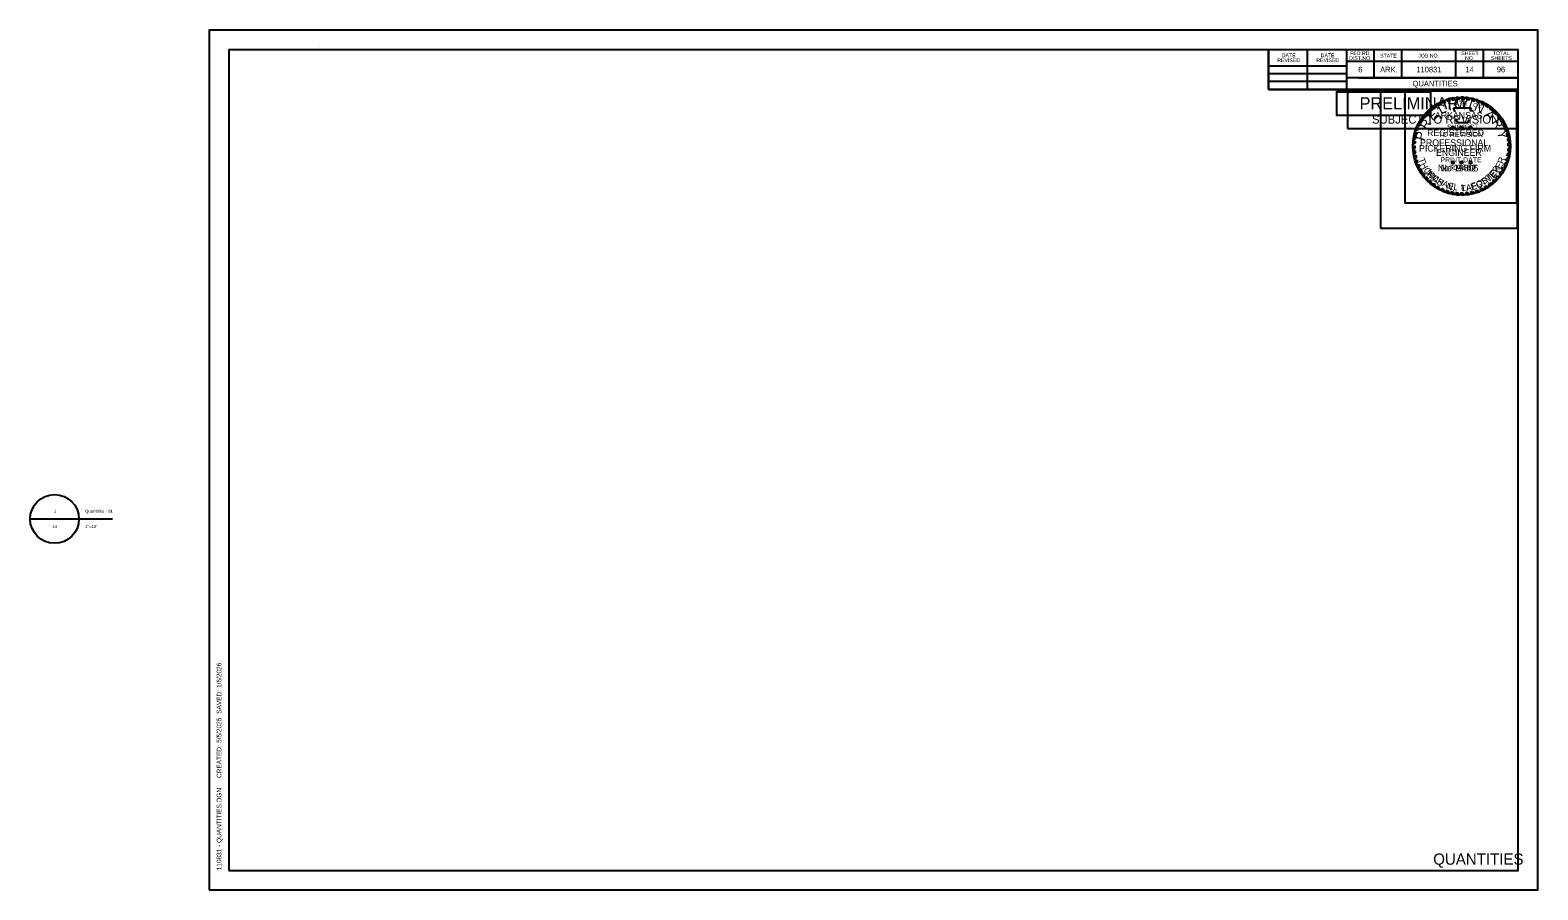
# Model space of a CAD drawing. Extents: x -0.19 to 1.42, y 0 to 0.92.
import ezdxf

# ---------------------------------------------------------------- set-up
doc = ezdxf.new("R2010")
doc.units = 0
for name, color, linetype in [('Default', 7, 'Continuous'), ('DSN_DRFT_Guideline-No-Plot', 7, 'Continuous'), ('SHET_Annotations', 7, 'Continuous'), ('SHET_Border-Lines', 7, 'Continuous'), ('SHET_Border-Text', 7, 'Continuous'), ('SHET_Stamp-Prelim', 7, 'Continuous'), ('SHET_Stamp-Seal', 7, 'Continuous'), ('STAMP_PE DIG SIG', 7, 'Continuous'), ('STAMP_PE_BACKGROUND', 7, 'Continuous'), ('STAMP_PE_FOSTER', 7, 'Continuous'), ('STAMP_PE_SEAL-INFO', 7, 'Continuous'), ('STAMP_PE_TAEGTMEYER', 7, 'Continuous'), ('STAMP_PRELIMINARY', 7, 'Continuous')]:
    doc.layers.add(name, color=color, linetype=linetype)

msp = doc.modelspace()

# ---------------------------------------------------------------- linework, layer by layer
at = {"layer": 'Default'}
for p, q in [((-0.191, 0.3955), (-0.1389, 0.3955)), ((-0.1648, 0.3955), (-0.1031, 0.3955))]:
    msp.add_line(p, q, dxfattribs=at)
msp.add_circle((-0.165, 0.3955), 0.026, dxfattribs=at)
at = {"layer": 'DSN_DRFT_Guideline-No-Plot'}
msp.add_lwpolyline([(0, 0), (1.4167, 0), (1.4167, 0.9167), (0, 0.9167)], close=True, dxfattribs=at)
at = {"layer": 'SHET_Border-Lines'}
for p, q in [((0.1176, 0.8988), (0.1176, 0.8988)), ((0.1176, 0.8988), (0.1176, 0.8988)), ((1.1296, 0.8534), (1.1296, 0.8958)), ((1.1711, 0.8534), (1.1711, 0.8958)), ((1.2127, 0.8958), (1.2127, 0.8534)), ((1.2417, 0.8958), (1.2417, 0.866)), ((1.2712, 0.8958), (1.2712, 0.866)), ((1.3289, 0.8958), (1.3289, 0.866)), ((1.3584, 0.8958), (1.3584, 0.866)), ((1.1296, 0.8786), (1.2127, 0.8786)), ((1.1296, 0.8706), (1.2127, 0.8706)), ((1.3958, 0.8832), (1.2127, 0.8832)), ((1.3958, 0.8833), (1.3958, 0.8833)), ((1.1296, 0.8622), (1.2127, 0.8622)), ((1.3958, 0.8534), (1.1296, 0.8534)), ((1.3958, 0.866), (1.2127, 0.866)), ((1.2252, 0.866), (1.3958, 0.866))]:
    msp.add_line(p, q, dxfattribs=at)
for points in [[(0.0208, 0.0208), (1.3958, 0.0208), (1.3958, 0.8958), (0.0208, 0.8958)], [(1.1296, 0.8534), (1.3958, 0.8534), (1.3958, 0.8958), (1.1296, 0.8958)]]:
    msp.add_lwpolyline(points, close=True, dxfattribs=at)
at = {"layer": 'SHET_Stamp-Prelim'}
msp.add_lwpolyline([(1.2137, 0.8119), (1.3948, 0.8119), (1.3948, 0.8524), (1.2137, 0.8524)], close=True, dxfattribs=at)
at = {"layer": 'SHET_Stamp-Seal'}
msp.add_line((1.3219, 0.7895), (1.3219, 0.7895), dxfattribs=at)
msp.add_lwpolyline([(1.249, 0.7057), (1.3948, 0.7057), (1.3948, 0.8524), (1.249, 0.8524)], close=True, dxfattribs=at)
at = {"layer": 'STAMP_PE DIG SIG'}
msp.add_lwpolyline([(1.2022, 0.8508), (1.3022, 0.8508), (1.3022, 0.8258), (1.2022, 0.8258)], close=True, dxfattribs=at)
at = {"layer": 'STAMP_PE_BACKGROUND'}
for points in [[(1.2022, 0.8517), (1.3022, 0.8517), (1.3022, 0.8258), (1.2022, 0.8258)], [(1.3942, 0.8517), (1.275, 0.8517), (1.275, 0.7325), (1.3942, 0.7325)]]:
    msp.add_lwpolyline(points, close=True, dxfattribs=at)
at = {"layer": 'STAMP_PE_SEAL-INFO'}
for p, q in [((1.3066, 0.8363), (1.309, 0.8352)), ((1.3087, 0.8377), (1.3112, 0.8365)), ((1.3112, 0.8391), (1.3138, 0.8378)), ((1.3137, 0.8403), (1.3158, 0.8387)), ((1.3165, 0.8415), (1.3181, 0.8397)), ((1.3184, 0.8422), (1.3206, 0.8405)), ((1.3217, 0.8432), (1.3233, 0.8413)), ((1.3239, 0.8438), (1.3259, 0.8418)), ((1.3266, 0.8443), (1.3283, 0.8422)), ((1.3295, 0.8447), (1.331, 0.8426)), ((1.3336, 0.8427), (1.3318, 0.8449)), ((1.3364, 0.8428), (1.3348, 0.845)), ((1.3389, 0.8426), (1.3375, 0.845)), ((1.3417, 0.8424), (1.3401, 0.8448)), ((1.3441, 0.842), (1.3427, 0.8445)), ((1.3473, 0.8413), (1.3463, 0.8439)), ((1.3495, 0.8407), (1.3486, 0.8433)), ((1.352, 0.8399), (1.3512, 0.8426)), ((1.3544, 0.839), (1.3536, 0.8418)), ((1.357, 0.8379), (1.3564, 0.8406)), ((1.3594, 0.8366), (1.359, 0.8394)), ((1.3616, 0.8353), (1.3614, 0.8381)), ((1.364, 0.8337), (1.3639, 0.8366)), ((1.2917, 0.8213), (1.2946, 0.8215)), ((1.293, 0.8232), (1.2959, 0.8232)), ((1.2946, 0.8253), (1.2977, 0.8254)), ((1.2965, 0.8276), (1.2994, 0.8274)), ((1.2983, 0.8295), (1.3014, 0.8293)), ((1.3002, 0.8313), (1.3028, 0.8306)), ((1.3021, 0.833), (1.3051, 0.8325)), ((1.3042, 0.8348), (1.3068, 0.8337)), ((1.3269, 0.8337), (1.3456, 0.8337)), ((1.3276, 0.832), (1.3269, 0.8337)), ((1.3281, 0.8303), (1.3276, 0.832)), ((1.3282, 0.8297), (1.3281, 0.8303)), ((1.3293, 0.8201), (1.3291, 0.8213)), ((1.331, 0.8201), (1.3293, 0.8201)), ((1.331, 0.8177), (1.331, 0.8201)), ((1.3429, 0.8213), (1.3424, 0.8196)), ((1.3456, 0.8337), (1.3443, 0.831)), ((1.3443, 0.831), (1.3478, 0.831)), ((1.3478, 0.831), (1.347, 0.8297)), ((1.366, 0.8322), (1.3662, 0.8349)), ((1.3685, 0.8301), (1.3687, 0.8331)), ((1.3703, 0.8285), (1.3707, 0.8313)), ((1.3723, 0.8264), (1.3727, 0.8294)), ((1.3738, 0.8247), (1.3746, 0.8273)), ((1.3756, 0.8223), (1.3764, 0.8251)), ((1.3769, 0.8206), (1.3779, 0.8232)), ((1.3786, 0.8178), (1.3796, 0.8205)), ((1.2847, 0.8048), (1.2873, 0.8059)), ((1.2853, 0.8071), (1.2879, 0.808)), ((1.2862, 0.8099), (1.2889, 0.8106)), ((1.287, 0.8121), (1.2898, 0.8129)), ((1.288, 0.8145), (1.2908, 0.8151)), ((1.2891, 0.8167), (1.2918, 0.8171)), ((1.2904, 0.8191), (1.2931, 0.8192)), ((1.3252, 0.8129), (1.3241, 0.8137)), ((1.3241, 0.8137), (1.3255, 0.8137)), ((1.3248, 0.8116), (1.3252, 0.8129)), ((1.3259, 0.8124), (1.3248, 0.8116)), ((1.3255, 0.8137), (1.3259, 0.815)), ((1.3259, 0.815), (1.3264, 0.8137)), ((1.327, 0.8116), (1.3259, 0.8124)), ((1.3264, 0.8137), (1.3277, 0.8137)), ((1.3277, 0.8137), (1.3266, 0.8129)), ((1.3266, 0.8129), (1.327, 0.8116)), ((1.3423, 0.8177), (1.331, 0.8177)), ((1.3347, 0.8129), (1.3336, 0.8137)), ((1.3336, 0.8137), (1.335, 0.8137)), ((1.3343, 0.8116), (1.3347, 0.8129)), ((1.3354, 0.8124), (1.3343, 0.8116)), ((1.335, 0.8137), (1.3354, 0.815)), ((1.3354, 0.815), (1.3358, 0.8137)), ((1.3365, 0.8116), (1.3354, 0.8124)), ((1.3358, 0.8137), (1.3372, 0.8137)), ((1.3372, 0.8137), (1.3361, 0.8129)), ((1.3361, 0.8129), (1.3365, 0.8116)), ((1.3424, 0.8196), (1.3423, 0.8177)), ((1.3442, 0.8129), (1.3431, 0.8137)), ((1.3431, 0.8137), (1.3445, 0.8137)), ((1.3438, 0.8116), (1.3442, 0.8129)), ((1.3449, 0.8124), (1.3438, 0.8116)), ((1.3445, 0.8137), (1.3449, 0.815)), ((1.3449, 0.815), (1.3453, 0.8137)), ((1.346, 0.8116), (1.3449, 0.8124)), ((1.3453, 0.8137), (1.3467, 0.8137)), ((1.3467, 0.8137), (1.3456, 0.8129)), ((1.3456, 0.8129), (1.346, 0.8116)), ((1.3797, 0.8157), (1.381, 0.8182)), ((1.381, 0.813), (1.3823, 0.8157)), ((1.3818, 0.8112), (1.3832, 0.8136)), ((1.3829, 0.8081), (1.3844, 0.8107)), ((1.3835, 0.8061), (1.3851, 0.8086)), ((1.3842, 0.8029), (1.386, 0.8054)), ((1.2857, 0.796), (1.2834, 0.7946)), ((1.2856, 0.7933), (1.2834, 0.7914)), ((1.2859, 0.7984), (1.2835, 0.7968)), ((1.2857, 0.791), (1.2835, 0.7892)), ((1.2862, 0.8008), (1.2838, 0.7996)), ((1.2858, 0.7882), (1.2838, 0.7862)), ((1.2867, 0.8034), (1.2841, 0.802)), ((1.3846, 0.8008), (1.3866, 0.8028)), ((1.3849, 0.7876), (1.3874, 0.7891)), ((1.385, 0.798), (1.387, 0.7998)), ((1.3851, 0.7956), (1.3873, 0.7973)), ((1.3852, 0.7927), (1.3875, 0.7945)), ((1.3852, 0.7905), (1.3875, 0.792)), ((1.2861, 0.7858), (1.2842, 0.7837)), ((1.2866, 0.7833), (1.2847, 0.7812)), ((1.2871, 0.7809), (1.2854, 0.7786)), ((1.2878, 0.7784), (1.2861, 0.7761)), ((1.2886, 0.7761), (1.287, 0.7738)), ((1.2895, 0.7737), (1.288, 0.7713)), ((1.3252, 0.7754), (1.3241, 0.7763)), ((1.3241, 0.7763), (1.3255, 0.7763)), ((1.3248, 0.7741), (1.3252, 0.7754)), ((1.3259, 0.7749), (1.3248, 0.7741)), ((1.3255, 0.7763), (1.3259, 0.7776)), ((1.3259, 0.7776), (1.3264, 0.7763)), ((1.327, 0.7741), (1.3259, 0.7749)), ((1.3264, 0.7763), (1.3277, 0.7763)), ((1.3277, 0.7763), (1.3266, 0.7754)), ((1.3266, 0.7754), (1.327, 0.7741)), ((1.3347, 0.7754), (1.3336, 0.7763)), ((1.3336, 0.7763), (1.335, 0.7763)), ((1.3343, 0.7741), (1.3347, 0.7754)), ((1.3354, 0.7749), (1.3343, 0.7741)), ((1.335, 0.7763), (1.3354, 0.7776)), ((1.3354, 0.7776), (1.3358, 0.7763)), ((1.3365, 0.7741), (1.3354, 0.7749)), ((1.3358, 0.7763), (1.3372, 0.7763)), ((1.3372, 0.7763), (1.3361, 0.7754)), ((1.3361, 0.7754), (1.3365, 0.7741)), ((1.3442, 0.7754), (1.3431, 0.7763)), ((1.3431, 0.7763), (1.3445, 0.7763)), ((1.3438, 0.7741), (1.3442, 0.7754)), ((1.3449, 0.7749), (1.3438, 0.7741)), ((1.3445, 0.7763), (1.3449, 0.7776)), ((1.3449, 0.7776), (1.3453, 0.7763)), ((1.346, 0.7741), (1.3449, 0.7749)), ((1.3453, 0.7763), (1.3467, 0.7763)), ((1.3467, 0.7763), (1.3456, 0.7754)), ((1.3456, 0.7754), (1.346, 0.7741)), ((1.3808, 0.7724), (1.3835, 0.7729)), ((1.382, 0.7753), (1.3847, 0.776)), ((1.3827, 0.7774), (1.3855, 0.7785)), ((1.3835, 0.7802), (1.3862, 0.7813)), ((1.3841, 0.7827), (1.3867, 0.7838)), ((1.3846, 0.7855), (1.3871, 0.7867)), ((1.2905, 0.7715), (1.2892, 0.769)), ((1.2918, 0.769), (1.2907, 0.7662)), ((1.2931, 0.7667), (1.2921, 0.7641)), ((1.2942, 0.765), (1.2936, 0.7619)), ((1.2958, 0.7628), (1.2952, 0.7598)), ((1.2975, 0.7607), (1.297, 0.7578)), ((1.2992, 0.7588), (1.2988, 0.7559)), ((1.301, 0.757), (1.3008, 0.754)), ((1.3702, 0.7573), (1.3727, 0.7566)), ((1.3716, 0.7588), (1.3743, 0.7583)), ((1.3738, 0.7612), (1.3763, 0.7608)), ((1.3755, 0.7634), (1.3783, 0.7634)), ((1.3774, 0.7662), (1.3801, 0.7661)), ((1.3783, 0.7677), (1.3811, 0.768)), ((1.3799, 0.7705), (1.3826, 0.7709)), ((1.3029, 0.7552), (1.3029, 0.7523)), ((1.3049, 0.7536), (1.305, 0.7507)), ((1.3068, 0.7522), (1.307, 0.7493)), ((1.3092, 0.7506), (1.3095, 0.7478)), ((1.3111, 0.7495), (1.3117, 0.7466)), ((1.3138, 0.7481), (1.3147, 0.7452)), ((1.3159, 0.7471), (1.3169, 0.7443)), ((1.3187, 0.7461), (1.3198, 0.7433)), ((1.321, 0.7453), (1.3222, 0.7426)), ((1.3238, 0.7445), (1.325, 0.7419)), ((1.326, 0.7441), (1.3274, 0.7415)), ((1.3288, 0.7436), (1.3302, 0.7411)), ((1.3313, 0.7433), (1.3328, 0.7409)), ((1.334, 0.7432), (1.3356, 0.7409)), ((1.3365, 0.7432), (1.3384, 0.741)), ((1.3394, 0.7433), (1.3412, 0.7412)), ((1.3419, 0.7436), (1.344, 0.7416)), ((1.3444, 0.744), (1.3465, 0.7421)), ((1.3471, 0.7446), (1.3492, 0.7427)), ((1.3497, 0.7453), (1.352, 0.7436)), ((1.3524, 0.7462), (1.3549, 0.7447)), ((1.3548, 0.7471), (1.3571, 0.7456)), ((1.3573, 0.7483), (1.36, 0.7471)), ((1.3596, 0.7494), (1.3619, 0.7481)), ((1.3619, 0.7508), (1.3644, 0.7497)), ((1.3639, 0.7521), (1.3663, 0.751)), ((1.3664, 0.754), (1.369, 0.7532)), ((1.3679, 0.7553), (1.3706, 0.7545))]:
    msp.add_line(p, q, dxfattribs=at)
for radius, start, end in [(0.0521, 123.6199, 126.5906), (0.0521, 117.6544, 120.8099), (0.0498, 115.6869, 119.1583), (0.0521, 111.3124, 114.7026), (0.0498, 110.3086, 113.1659), (0.0521, 105.2339, 109.0352), (0.0498, 104.0352, 107.3615), (0.0521, 99.7525, 102.7765), (0.0498, 98.258, 101.0329), (0.0521, 93.9381, 96.5517), (0.0498, 92.1102, 95.0367), (0.0521, 87.7298, 90.6707), (0.0498, 85.9628, 88.9097), (0.0521, 81.9732, 84.8236), (0.0498, 79.9264, 82.696), (0.0521, 75.3125, 77.9426), (0.0498, 73.5575, 76.2314), (0.0521, 69.6061, 72.3058), (0.0498, 67.6248, 70.504), (0.0521, 63.1329, 66.2704), (0.0498, 61.1558, 64.3784), (0.0521, 56.9003, 60.0942), (0.0521, 147.0072, 149.899), (0.0521, 141.6056, 144.4486), (0.0498, 145.0197, 148.2104), (0.0498, 139.301, 142.5873), (0.0521, 135.4021, 138.3031), (0.0498, 133.1331, 136.2562), (0.0521, 129.7326, 132.5376), (0.0498, 127.5297, 130.9683), (0.0498, 121.9746, 125.11), (0.0498, 54.9238, 58.2702), (0.0498, 48.3016, 52.0395), (0.0521, 50.3492, 53.7159), (0.0498, 42.2212, 45.5512), (0.0521, 44.3405, 47.3929), (0.0498, 36.135, 39.5311), (0.0521, 38.1247, 41.2316), (0.0498, 29.9032, 33.6645), (0.0521, 31.9614, 35.4294), (0.0521, 164.3068, 166.894), (0.0521, 158.4077, 161.0701), (0.0498, 162.4331, 165.0013), (0.0521, 152.864, 155.5189), (0.0498, 156.3402, 159.2319), (0.0498, 151.0315, 153.573), (0.0498, 23.7732, 27.2211), (0.0521, 25.9391, 29.0125), (0.0498, 17.6802, 21.4251), (0.0521, 19.9538, 23.3141), (0.0498, 11.5444, 15.2364), (0.0521, 13.8421, 17.4447), (0.0521, 175.7409, 178.2066), (0.0521, 181.7251, 184.1626), (0.0521, 170.0003, 172.6878), (0.0498, 179.6454, 182.2633), (0.0498, 173.73, 176.4734), (0.0498, 185.4539, 188.234), (0.0498, 167.9048, 170.9039), (0.0498, 5.7599, 9.0606), (0.0498, 353.8632, 357.1274), (0.0498, 359.7329, 3.0639), (0.0521, 7.5852, 10.8621), (0.0521, 1.7215, 4.7268), (0.0521, 355.7156, 358.9569), (0.0521, 187.4204, 190.1927), (0.0521, 193.0369, 195.9973), (0.0521, 198.8967, 201.6281), (0.0498, 191.2274, 193.9858), (0.0498, 196.9675, 199.8353), (0.0498, 202.7761, 205.4791), (0.0498, 335.6038, 339.1858), (0.0498, 341.777, 345.0925), (0.0521, 337.3837, 340.9933), (0.0498, 348.0778, 351.3435), (0.0521, 343.8925, 347.035), (0.0521, 349.8305, 353.0885), (0.0521, 204.5479, 207.4328), (0.0521, 210.8636, 213.6571), (0.0498, 208.7883, 211.7934), (0.0521, 216.6115, 219.491), (0.0498, 214.1838, 217.2747), (0.0521, 222.48, 225.3801), (0.0498, 220.3909, 223.3056), (0.0498, 226.2494, 229.2407), (0.0498, 310.7744, 314.3161), (0.0521, 312.4518, 315.6633), (0.0498, 316.6531, 320.3711), (0.0521, 318.2846, 321.8043), (0.0498, 323.5851, 327.4407), (0.0498, 329.5549, 333.2076), (0.0521, 325.4405, 328.9872), (0.0521, 331.4037, 334.9332), (0.0521, 228.3665, 231.348), (0.0498, 232.229, 234.9336), (0.0521, 234.295, 236.9452), (0.0498, 238.2223, 240.8353), (0.0521, 240.1977, 242.8613), (0.0498, 244.3204, 246.9486), (0.0521, 246.576, 249.1558), (0.0498, 250.3491, 253.1216), (0.0521, 252.5967, 255.3252), (0.0498, 256.505, 259.1192), (0.0521, 258.4433, 261.1398), (0.0498, 262.3783, 265.2012), (0.0521, 264.1978, 267.1009), (0.0498, 268.3215, 271.277), (0.0521, 270.2548, 273.3361), (0.0498, 274.6157, 277.4486), (0.0521, 276.4239, 279.4357), (0.0498, 280.3459, 283.5814), (0.0521, 282.3199, 285.3702), (0.0498, 286.6423, 289.9783), (0.0521, 288.5709, 291.9733), (0.0498, 292.8745, 296.1185), (0.0521, 294.6481, 298.2166), (0.0498, 299.0768, 302.1724), (0.0521, 300.621, 303.8703), (0.0498, 304.823, 308.5143), (0.0521, 306.3721, 310.208)]:
    msp.add_arc((1.3354, 0.793), radius, start, end, dxfattribs=at)
at = {"layer": 'STAMP_PRELIMINARY'}
msp.add_circle((1.3354, 0.793), 0.0521, dxfattribs=at)

# ---------------------------------------------------------------- texts
at = {"layer": 'Default'}
for s, height, p in [('1', 0.00328, (-0.1658, 0.4021)), ('Quantities - 01', 0.003281, (-0.1324, 0.4021)), ('14', 0.00328, (-0.1672, 0.3857)), ('1"=10\'', 0.00328, (-0.1324, 0.3857))]:
    msp.add_text(s, height=height, dxfattribs=at).set_placement(p)
at = {"layer": 'SHET_Annotations'}
for s, height, p in [('6', 0.006, (1.2252, 0.8716)), ('ARK.', 0.006, (1.2485, 0.8716)), ('110831', 0.006, (1.2871, 0.8716)), ('14', 0.006, (1.3394, 0.8716)), ('96', 0.006, (1.3729, 0.8717)), ('QUANTITIES', 0.006, (1.2831, 0.8567)), ('QUANTITIES', 0.012, (1.3051, 0.0268))]:
    msp.add_text(s, height=height, dxfattribs=at).set_placement(p)
at = {"layer": 'SHET_Border-Text'}
for s, p in [('REVISED', (1.1388, 0.8826)), ('DATE', (1.1436, 0.8878)), ('REVISED', (1.1804, 0.8826)), ('DATE', (1.1851, 0.8878)), ('DIST.NO.', (1.2154, 0.8849)), ('FED.RD.', (1.2165, 0.8901)), ('STATE', (1.2485, 0.8875)), ('JOB NO.', (1.2891, 0.8875)), ('SHEET', (1.335, 0.8901)), ('NO.', (1.339, 0.8849)), ('SHEETS', (1.3668, 0.8849)), ('TOTAL', (1.3686, 0.8901))]:
    msp.add_text(s, height=0.004, dxfattribs=at).set_placement(p)
for s, p in [('1/6/2026', (0.0129, 0.2153)), ('  SAVED: ', (0.0129, 0.1839)), ('5/5/2025', (0.0129, 0.1567)), ('     CREATED: ', (0.0129, 0.1097)), ('110831 - QUANTITIES.DGN', (0.0129, 0.0208))]:
    msp.add_text(s, height=0.005, rotation=90, dxfattribs=at).set_placement(p)
at = {"layer": 'SHET_Stamp-Prelim'}
for s, height, p in [('PRELIMINARY', 0.013, (1.2266, 0.8322)), ('SUBJECT TO REVISION', 0.009, (1.2398, 0.817))]:
    msp.add_text(s, height=height, dxfattribs=at).set_placement(p)
at = {"layer": 'STAMP_PE_FOSTER'}
msp.add_text('No. 9402', height=0.00698, dxfattribs=at).set_placement((1.313, 0.7661))
for s, rotation, p in [('R', 54.5031, (1.373, 0.764)), ('M', 308.339, (1.297, 0.7652)), ('I', 314.1842, (1.3014, 0.7599)), ('C', 319.8733, (1.3034, 0.7579)), ('H', 327.7235, (1.3086, 0.7538)), ('A', 335.7276, (1.3141, 0.7506)), ('O', 23.719, (1.3526, 0.7487)), ('S', 31.7234, (1.3588, 0.7517)), ('T', 39.4194, (1.3641, 0.7552)), ('E', 46.9613, (1.3689, 0.7594)), ('E', 343.5779, (1.3204, 0.748)), ('L', 350.8115, (1.3263, 0.7464)), ('L', 1.2666, (1.3349, 0.7455)), ('.', 6.8035, (1.3408, 0.7459)), ('F', 15.8691, (1.3468, 0.7469))]:
    msp.add_text(s, height=0.0067, rotation=rotation, dxfattribs=at).set_placement(p)
at = {"layer": 'STAMP_PE_SEAL-INFO'}
for s, rotation, p in [('S', 23.5541, (1.3164, 0.8327)), ('T', 16.311, (1.3216, 0.8347)), ('A', 9.0679, (1.3269, 0.8361)), ('T', 1.8248, (1.3325, 0.8369)), ('E', 355.2002, (1.3375, 0.8369)), ('O', 342.2506, (1.3472, 0.8354)), ('F', 335.0075, (1.3526, 0.8335))]:
    msp.add_text(s, height=0.00436, rotation=rotation, dxfattribs=at).set_placement(p)
for s, height, p in [('ARKANSAS', 0.00698, (1.3069, 0.8223)), ('REGISTERED', 0.00698, (1.2986, 0.8038)), ('PROFESSIONAL', 0.006983, (1.2911, 0.7932)), ('ENGINEER', 0.00698, (1.3081, 0.7826))]:
    msp.add_text(s, height=height, dxfattribs=at).set_placement(p)
at = {"layer": 'STAMP_PE_TAEGTMEYER'}
for s, rotation, p in [('T', 289.646, (1.289, 0.7791)), ('H', 296.7339, (1.291, 0.7736)), ('Y', 53.9986, (1.3733, 0.7628)), ('E', 63.0984, (1.377, 0.768)), ('R', 69.57, (1.3798, 0.7735)), ('O', 303.7708, (1.2943, 0.7674)), ('M', 314.2033, (1.298, 0.7621)), ('A', 321.0594, (1.3034, 0.7567)), ('S', 327.8239, (1.308, 0.7531)), ('G', 23.3052, (1.3522, 0.7475)), ('T', 31.466, (1.3583, 0.7503)), ('M', 39.3, (1.3633, 0.7533)), ('E', 46.8094, (1.3692, 0.7582)), ('N', 344.2727, (1.3186, 0.7474)), ('.', 350.6464, (1.3254, 0.7456)), ('T', 3.0061, (1.3347, 0.7445)), ('A', 8.9826, (1.3405, 0.7448)), ('E', 17.6836, (1.3463, 0.7457))]:
    msp.add_text(s, height=0.00698, rotation=rotation, dxfattribs=at).set_placement(p)
msp.add_text('No. 19605', height=0.00698, dxfattribs=at).set_placement((1.3101, 0.7661))
at = {"layer": 'STAMP_PRELIMINARY'}
for s, rotation, p in [('L', 25.513, (1.3131, 0.8266)), ('I', 12.5248, (1.3217, 0.8309)), ('M', 3.1074, (1.3278, 0.8326)), ('I', 342.3164, (1.3416, 0.833)), ('N', 333.9382, (1.3478, 0.8315)), ('R', 56.2292, (1.2984, 0.8095)), ('E', 42.3578, (1.3048, 0.8192)), ('A', 315.6579, (1.3591, 0.8257)), ('R', 301.3831, (1.3668, 0.8184)), ('P', 73.913, (1.2953, 0.7982)), ('Y', 283.2593, (1.3729, 0.8084))]:
    msp.add_text(s, height=0.0101, rotation=rotation, dxfattribs=at).set_placement(p)
for s, height, p in [('TO REVISION', 0.005363, (1.3105, 0.8028)), ('SUBJECT', 0.00536, (1.3198, 0.8106)), ('PICKERING FIRM', 0.006983, (1.29, 0.7872)), ('PRINT DATE', 0.00536, (1.3128, 0.7757)), ('$DATE$', 0.00536, (1.3222, 0.768))]:
    msp.add_text(s, height=height, dxfattribs=at).set_placement(p)

doc.saveas('drawing.dxf')
